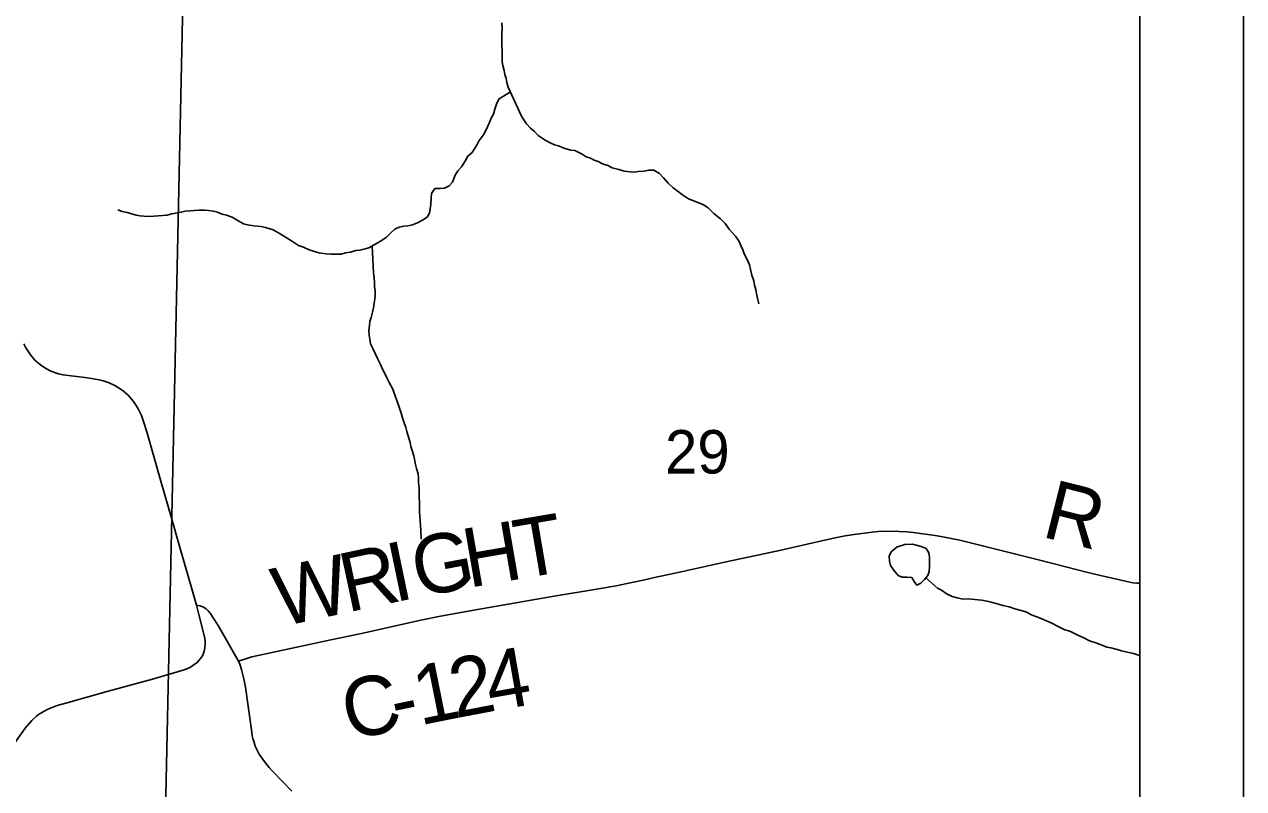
# Model space of a CAD drawing. Extents: x 0 to 34, y -8.9 to 22.
# Drawn here: x 29.442 to 30.617, y 10.352 to 11.088 of the extents above; entities that cross this region are included whole.
import ezdxf

# ---------------------------------------------------------------- set-up
doc = ezdxf.new("R2010")
doc.units = 0
for name, color, linetype in [('GM_X_Corporation', 7, 'Continuous'), ('GM_X_County_Road', 7, 'Continuous'), ('GM_X_County_Road_Text', 7, 'Continuous'), ('GM_X_Minor_River', 7, 'Continuous'), ('GM_X_Section_Text', 7, 'Continuous'), ('GM_X_State_Route', 7, 'Continuous'), ('SH_Data', 7, 'Continuous')]:
    doc.layers.add(name, color=color, linetype=linetype)

msp = doc.modelspace()

# ---------------------------------------------------------------- linework, layer by layer
at = {"layer": 'GM_X_Corporation'}
for points in [[(28.7046, 7.104), (30.5167, 7.104), (30.5167, 13.904), (28.8143, 13.904), (28.8122, 13.7561), (28.8049, 13.053), (28.7787, 12.0377), (28.7786, 12.0342), (28.7779, 11.9899), (28.7762, 11.8872), (28.7797, 11.7437), (28.7775, 11.7346), (28.7754, 11.6346), (28.7651, 11.3014), (28.7622, 11.1187), (28.7609, 11.0119), (28.7377, 10.2012), (28.7308, 9.4444), (28.7238, 9.1729), (28.7123, 8.2818)], [(28.7046, 7.104), (30.5167, 7.104), (30.5167, 12.0118), (29.364, 12.0313), (29.2718, 12.0324), (28.9225, 12.0359), (28.8128, 12.0371), (28.7787, 12.0377), (28.7786, 12.0342), (28.7779, 11.9899), (28.7762, 11.8872), (28.7797, 11.7437), (28.7775, 11.7346), (28.7754, 11.6346), (28.7651, 11.3014), (28.7622, 11.1187), (28.7609, 11.0119), (28.7377, 10.2012), (28.7308, 9.4444), (28.7238, 9.1729), (28.7123, 8.2818)], [(29.5966, 11.1991), (29.575, 10.1808), (28.7457, 10.2071), (28.7671, 11.2169)], [(30.5167, 10.1744), (30.5167, 11.1804), (29.5966, 11.1991), (29.575, 10.1808)]]:
    msp.add_lwpolyline(points, close=True, dxfattribs=at)
at = {"layer": 'GM_X_County_Road'}
for points in [[(29.6485, 10.475), (29.6573, 10.4782), (29.6614, 10.4793), (29.7135, 10.4905), (29.7374, 10.4958), (29.7669, 10.5019), (29.824, 10.5145), (29.8431, 10.5184), (29.8752, 10.5242), (29.9027, 10.529), (29.9507, 10.5373), (29.9952, 10.5448), (30.0124, 10.5478), (30.0273, 10.5508), (30.0383, 10.5531), (30.0492, 10.5556), (30.0748, 10.5613), (30.1181, 10.5708), (30.1696, 10.5817), (30.2074, 10.5903), (30.2232, 10.594), (30.2329, 10.5958), (30.2438, 10.5975), (30.2489, 10.5982), (30.2588, 10.5994), (30.2649, 10.5999), (30.2716, 10.6002), (30.2848, 10.6001), (30.2927, 10.5996), (30.2985, 10.599), (30.3194, 10.5961), (30.3286, 10.5944), (30.3351, 10.5933), (30.3432, 10.5915), (30.3563, 10.5884), (30.3881, 10.5804), (30.4177, 10.5729), (30.4453, 10.5659), (30.4653, 10.5609), (30.4787, 10.5577), (30.5041, 10.5518), (30.51, 10.5507), (30.5139, 10.5503), (30.5167, 10.5501)], [(29.6485, 10.475), (29.6287, 10.5096), (29.6234, 10.5179), (29.6215, 10.521), (29.6193, 10.5236), (29.6173, 10.5256), (29.6147, 10.5273), (29.6115, 10.5285), (29.608, 10.5291)], [(29.6999, 10.35), (29.6811, 10.3694), (29.678, 10.3729), (29.6741, 10.3776), (29.6705, 10.3825), (29.6684, 10.3857), (29.6661, 10.39), (29.6646, 10.3934), (29.6634, 10.3969), (29.6623, 10.4006), (29.6616, 10.4033), (29.6608, 10.409), (29.6553, 10.45), (29.6537, 10.4581), (29.6514, 10.4672), (29.6497, 10.4722), (29.6485, 10.475)]]:
    msp.add_lwpolyline(points, dxfattribs=at)
at = {"layer": 'GM_X_Minor_River'}
for points in [[(29.9022, 11.0899), (29.9023, 11.0842), (29.9021, 11.0789), (29.9025, 11.0523), (29.903, 11.0486), (29.9042, 11.044), (29.905, 11.0399), (29.9062, 11.0361), (29.907, 11.0323), (29.9083, 11.0278), (29.9212, 10.9999), (29.9232, 10.9962), (29.9259, 10.9924), (29.9298, 10.9883), (29.9336, 10.985), (29.9371, 10.9812), (29.944, 10.9768), (29.9486, 10.9742), (29.9528, 10.9724), (29.9566, 10.9713), (29.9627, 10.9688), (29.9687, 10.967), (29.9725, 10.9667), (29.9794, 10.9634), (29.9832, 10.9608), (29.9874, 10.9594), (29.9912, 10.9575), (29.995, 10.9561), (29.9992, 10.9539), (30.0042, 10.9524), (30.0084, 10.9502), (30.0149, 10.9485), (30.0198, 10.947), (30.0259, 10.9464), (30.0297, 10.9461), (30.0338, 10.9465), (30.0391, 10.947), (30.0433, 10.9478), (30.0485, 10.9479), (30.0539, 10.9446), (30.0578, 10.9405), (30.0624, 10.9353), (30.067, 10.9308), (30.0724, 10.9271), (30.0762, 10.9241), (30.082, 10.9204), (30.0877, 10.9179), (30.0919, 10.9164), (30.0964, 10.9146), (30.101, 10.9117), (30.1068, 10.9057), (30.1126, 10.9009), (30.1172, 10.8964), (30.1211, 10.8911), (30.1272, 10.8844), (30.1307, 10.8792), (30.1323, 10.8754), (30.1343, 10.8713), (30.1355, 10.8675), (30.1386, 10.8611), (30.1406, 10.8566), (30.1418, 10.8524), (30.143, 10.8467), (30.1447, 10.8415), (30.1455, 10.8373), (30.1467, 10.8328), (30.1479, 10.8275), (30.1488, 10.8229), (30.1496, 10.8192)], [(29.9104, 11.0232), (29.8994, 11.0166), (29.8972, 11.0124), (29.8954, 11.0067), (29.894, 11.0017), (29.8918, 10.9979), (29.89, 10.9933), (29.887, 10.9868), (29.8845, 10.9818), (29.8804, 10.9764), (29.8782, 10.9726), (29.8734, 10.9649), (29.8693, 10.9614), (29.8671, 10.9572), (29.8631, 10.9511), (29.8597, 10.9472), (29.8572, 10.943), (29.8546, 10.9365), (29.8513, 10.9327), (29.8468, 10.9307), (29.8426, 10.9302), (29.8377, 10.9301), (29.8344, 10.9255), (29.8341, 10.9213), (29.8338, 10.9153), (29.8331, 10.9107), (29.8325, 10.9065), (29.8303, 10.9027), (29.8258, 10.8996), (29.8209, 10.8972), (29.816, 10.8952), (29.8115, 10.8944), (29.8077, 10.8939), (29.8032, 10.8931), (29.7991, 10.8911), (29.7953, 10.8876), (29.7909, 10.8834), (29.786, 10.8799), (29.774, 10.8732), (29.7703, 10.872), (29.7654, 10.8708), (29.7616, 10.8704), (29.7563, 10.8691), (29.7514, 10.8683), (29.7473, 10.8671), (29.7374, 10.8669), (29.7329, 10.8672), (29.7257, 10.8682), (29.7207, 10.87), (29.7165, 10.8711), (29.7112, 10.8736), (29.7062, 10.8754), (29.7005, 10.8791), (29.6886, 10.8865), (29.6818, 10.8906), (29.6745, 10.8927), (29.67, 10.8938), (29.6632, 10.8944), (29.6571, 10.8954), (29.6533, 10.8961), (29.6487, 10.8987), (29.6422, 10.9028), (29.6369, 10.9046), (29.6327, 10.9056), (29.6281, 10.9075), (29.6243, 10.9085), (29.6194, 10.9092), (29.6156, 10.9095), (29.6107, 10.9094), (29.6058, 10.909), (29.602, 10.9089), (29.5971, 10.9084), (29.5933, 10.9076), (29.5842, 10.9059), (29.5793, 10.9047), (29.5714, 10.9038), (29.5669, 10.9037), (29.562, 10.9033), (29.5574, 10.9036), (29.5536, 10.9039), (29.5498, 10.9046), (29.5411, 10.9071), (29.5365, 10.9081), (29.5323, 10.9096)], [(29.7772, 10.875), (29.7786, 10.849), (29.7791, 10.8441), (29.7795, 10.8399), (29.7796, 10.8358), (29.7801, 10.8316), (29.7801, 10.8278), (29.7798, 10.8236), (29.7791, 10.8198), (29.7785, 10.8152), (29.7774, 10.8111), (29.7763, 10.8061), (29.7749, 10.8023), (29.7746, 10.7985), (29.7739, 10.7935), (29.7744, 10.789), (29.7748, 10.7852), (29.7757, 10.7807), (29.778, 10.7754), (29.7804, 10.7709), (29.7827, 10.766), (29.7851, 10.7607), (29.7875, 10.7558), (29.7894, 10.7521), (29.7918, 10.7472), (29.7937, 10.7434), (29.7969, 10.7378), (29.7981, 10.734), (29.8024, 10.7227), (29.8052, 10.714), (29.8064, 10.7095), (29.808, 10.7046), (29.8096, 10.7001), (29.8105, 10.6963), (29.8137, 10.6857), (29.8145, 10.6819), (29.8161, 10.677), (29.8173, 10.6729), (29.819, 10.6645), (29.8198, 10.6608), (29.8214, 10.6555), (29.8218, 10.6517), (29.8219, 10.6471), (29.8224, 10.6422), (29.8228, 10.6187), (29.8232, 10.6149), (29.8233, 10.6104), (29.8238, 10.6054), (29.8242, 10.6013), (29.8244, 10.5925)], [(30.3124, 10.5576), (30.3094, 10.5537), (30.3057, 10.5503), (30.3019, 10.5483), (30.2992, 10.552), (30.2969, 10.5558), (30.2923, 10.5561), (30.2878, 10.556), (30.284, 10.5578), (30.2794, 10.5631), (30.2766, 10.5672), (30.2754, 10.5713), (30.2753, 10.5763), (30.2772, 10.5805), (30.2828, 10.5851), (30.2865, 10.5863), (30.2903, 10.5875), (30.2978, 10.5877), (30.3024, 10.5866), (30.3062, 10.5856), (30.3108, 10.5837), (30.3135, 10.5796), (30.314, 10.5754), (30.3141, 10.5663), (30.3138, 10.5614), (30.3124, 10.5576)], [(30.3107, 10.5554), (30.3217, 10.5456), (30.3255, 10.5434), (30.3312, 10.5397), (30.3358, 10.5375), (30.3408, 10.5361), (30.3461, 10.535), (30.3514, 10.5351), (30.3643, 10.5338), (30.3696, 10.5328), (30.3734, 10.5321), (30.3806, 10.53), (30.3848, 10.5289), (30.3909, 10.5275), (30.3962, 10.5257), (30.4011, 10.5243), (30.4068, 10.5225), (30.4129, 10.5195), (30.4202, 10.517), (30.4274, 10.5137), (30.432, 10.5119), (30.4366, 10.5093), (30.4446, 10.5053), (30.4492, 10.5039), (30.4564, 10.5006), (30.4633, 10.4973), (30.4682, 10.4947), (30.4743, 10.4929), (30.4812, 10.4904), (30.485, 10.4886), (30.4888, 10.4879), (30.4949, 10.4865), (30.4991, 10.485), (30.5032, 10.484), (30.5105, 10.4826), (30.5154, 10.4808), (30.5167, 10.4806)]]:
    msp.add_lwpolyline(points, dxfattribs=at)
at = {"layer": 'GM_X_State_Route'}
msp.add_lwpolyline([(29.4337, 10.3974), (29.443, 10.4107), (29.4494, 10.4179), (29.454, 10.4223), (29.4557, 10.4237), (29.4596, 10.4261), (29.464, 10.4285), (29.4688, 10.4306), (29.4738, 10.4324), (29.4822, 10.4348), (29.5207, 10.4455), (29.5656, 10.4579), (29.5962, 10.4669), (29.5988, 10.4678), (29.6022, 10.4694), (29.6045, 10.4709), (29.6088, 10.4741), (29.6127, 10.479), (29.6136, 10.4804), (29.6148, 10.483), (29.6154, 10.4848), (29.616, 10.4876), (29.6164, 10.492), (29.6163, 10.495), (29.6158, 10.4985), (29.6102, 10.52), (29.608, 10.5291), (29.6035, 10.5447), (29.5963, 10.5692), (29.5908, 10.5881), (29.5841, 10.6119), (29.5737, 10.6484), (29.5601, 10.6961), (29.5574, 10.7051), (29.5549, 10.7116), (29.5519, 10.7181), (29.5498, 10.7214), (29.5472, 10.7251), (29.542, 10.7312), (29.5376, 10.7351), (29.5344, 10.7375), (29.5293, 10.7406), (29.524, 10.7431), (29.518, 10.7452), (29.5141, 10.7461), (29.503, 10.7479), (29.4795, 10.7508), (29.4752, 10.7517), (29.472, 10.7527), (29.467, 10.7548), (29.4618, 10.7577), (29.4578, 10.7605), (29.4524, 10.7651), (29.4482, 10.7701), (29.4455, 10.774), (29.4437, 10.7769), (29.4418, 10.7806)], dxfattribs=at)
at = {"layer": 'SH_Data'}
for points in [[(23.6167, 14.004), (30.6167, 14.004), (30.6167, 7.004), (23.6167, 7.004)], [(23.7167, 13.904), (30.5167, 13.904), (30.5167, 7.104), (23.7167, 7.104)]]:
    msp.add_lwpolyline(points, close=True, dxfattribs=at)

# ---------------------------------------------------------------- texts
at = {"layer": 'GM_X_County_Road_Text'}
for s, rotation, p in [('R', 345.9212, (30.4208, 10.5953)), ('T', 9.7195, (29.9193, 10.5542)), ('H', 9.8067, (29.8701, 10.5457)), ('G', 10.7734, (29.8212, 10.5364)), ('R', 12.1351, (29.7531, 10.5219)), ('I', 11.7769, (29.7986, 10.5317)), ('W', 12.1591, (29.6888, 10.508)), ('2', 10.7629, (29.8573, 10.4201)), ('4', 9.9371, (29.8914, 10.4266)), ('1', 11.3936, (29.8231, 10.4132)), ('C', 11.959, (29.7548, 10.3988)), ('-', 11.7998, (29.8004, 10.4085))]:
    msp.add_text(s, height=0.0568, rotation=rotation, dxfattribs=at).set_placement(p)
at = {"layer": 'GM_X_Section_Text'}
msp.add_text('29', height=0.04186, rotation=0, dxfattribs=at).set_placement((30.0593, 10.6558))

doc.saveas('drawing.dxf')
